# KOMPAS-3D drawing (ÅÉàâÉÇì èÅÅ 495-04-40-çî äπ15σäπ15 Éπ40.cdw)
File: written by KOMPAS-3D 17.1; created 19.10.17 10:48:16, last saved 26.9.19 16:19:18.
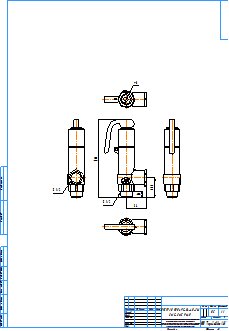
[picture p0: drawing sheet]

Sheet 1: A2, portrait

Title block, sheet 1: name: ПРЕГРАН КПП 495-04-40-ЗМ / Ду15хДу15 Ру40; material: Сталь 20  ГОСТ 1050-2013; mass: 0,5; sheets: 1; sheet format: A2; stored path: C:\Users\kka\KOMPAS_Work\!Trash\Прегран КПП 495\ПРЕГРАН КПП 495-04-40-ЗМ\KOMPAS 2D\Прегран КПП 495 Ду15хДу15 Ру40.cdw

Views: Спереди 6, Спереди, Проекционный вид 7, Проекционный вид 8, Проекционный вид 9, Проекционный вид 10
Referenced files in C:\Users\kka\KOMPAS_Work\!Trash\Прегран КПП 495\ПРЕГРАН КПП 495-04-40-ЗМ\KOMPAS 3D\: ПРЕГРАН КПП 495-04-40-ЗМ Ду15хДу15 Ру40.m3d
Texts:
  kka
  adl
  Рама для чертежей
  Лит-Масса-Масштаб
  Материал-Предприятие
  Масштаб
  Изм.
  Лист
  № докум.
  Подп.
  Дата
  Лит.
  Разраб.
  Пров.
  Т.контр.
  Листов
  Внимание! Данный продукт является объектом авторского права ООО «Торговый Дом АДЛ».
  Запрещается изменение, копирование, распространение
  (в том числе путем копирования на другие сайты и ресурсы в Интернете)
  или любое иное использование информации и объектов без предварительного
  согласия правообладателя (ООО «Торговый Дом АДЛ»).
  Н.контр.
  Утв.
  ООО "Торговый дом АДЛ"
  Изменение
  Номер документа
  Подпись
  Обозначение документа
  Наименование изделия
  Масса изделия по ГОСТ 2.109-73
  Порядковый номер листа
  Общее количество листов в документе
  Характер работы, выполненной лицом, подписавшим документ
  Наименование или индекс предприятия, выпускающего документ
  Инв. № подл.
  Подп. и дата
  Взам. инв. №
  Инв. № дубл.
  Инвентарный номер подлинника по ГОСТ 2.501-68
  Подпись принявшего подлинник в отдел технической документации
  Инвентарный номер подлинника, взамен которого выпущен данный подлинник
  Инвентарный номер дубликата по ГОСТ 2.502-68
  Подпись принявшего дубликат в отдел технической документации
  Справ. №
  Перв. примен.
  Обозначение документа, взамен или на основании которого выпущен данный документ
  Обозначение документа, в котором впервые записан данный документ
  Подпись лица, копировавшего чертеж
  Обозначение формата листа
  !Рама для чертежа
Dimensions and other numbers on the sheet: 35,5; 12; 36; 139; 8; 0,5; 1:1; 1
